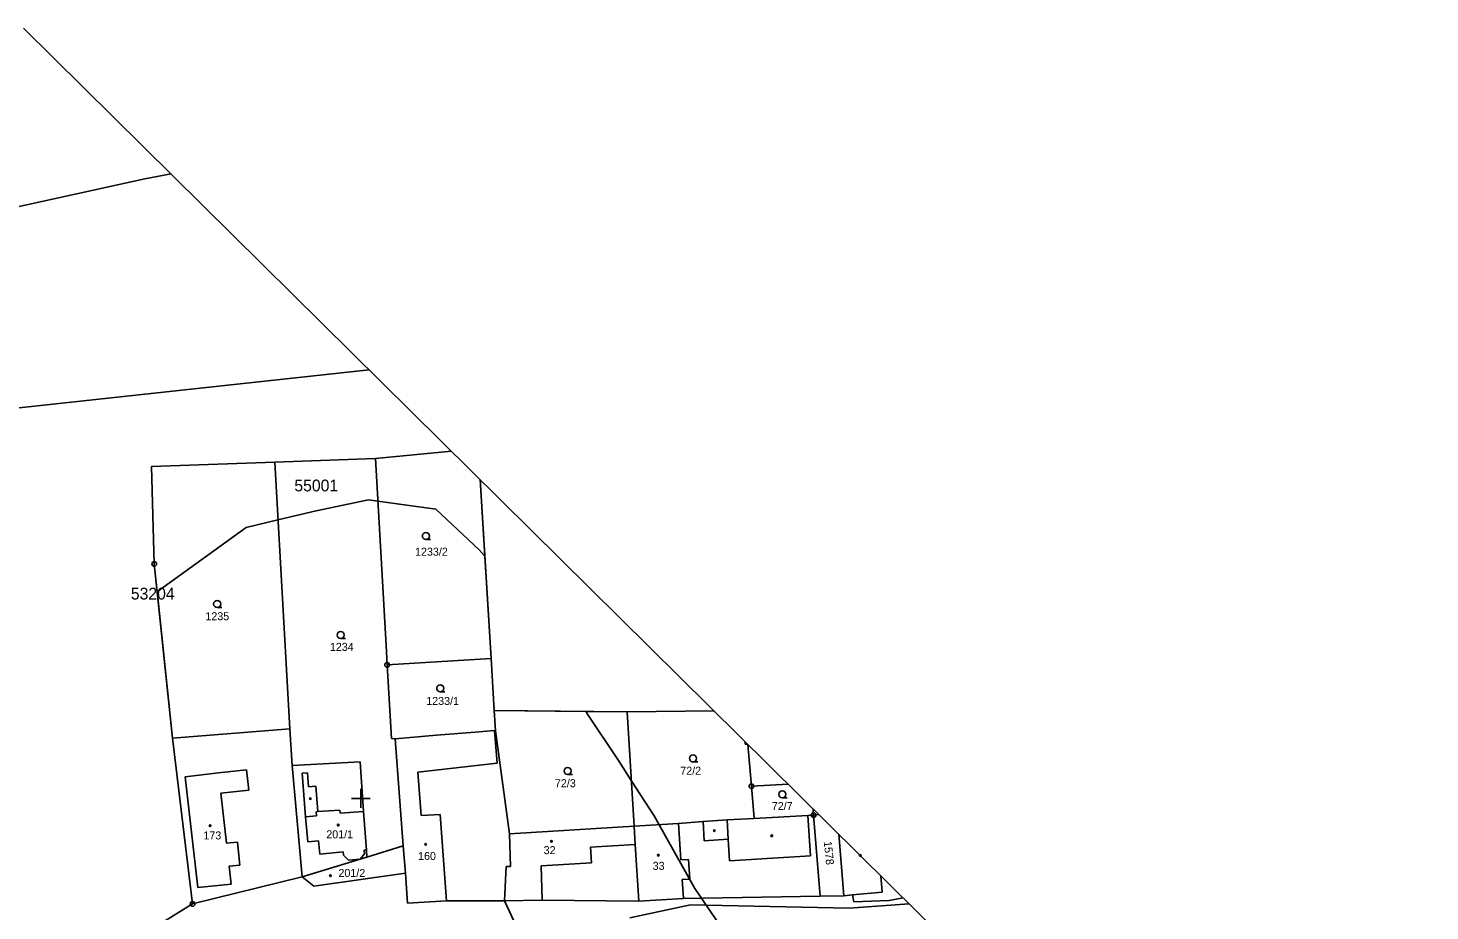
# Model space of a CAD drawing. Extents: x -777175 to -776673, y -1110537 to -1110036.
# Drawn here: x -776970.6 to -776672.9, y -1110223.9 to -1110036.4 of the extents above; entities that cross this region are included whole.
import ezdxf

# ---------------------------------------------------------------- set-up
doc = ezdxf.new("R2010")
doc.units = 0
for name, color, linetype in [('BPEJ', 7, 'Continuous'), ('Katastr_Hranice parcel', 7, 'Continuous'), ('Katastr_Parcelní čísla', 7, 'Continuous'), ('Katastr_Slučkované čáry', 7, 'Continuous'), ('Katastr_Značky kultur', 7, 'Continuous'), ('čtvercová síť', 7, 'Continuous')]:
    doc.layers.add(name, color=color, linetype=linetype)

# ---------------------------------------------------------------- blocks, each defined once
blk = doc.blocks.new('C691')
at = {"layer": 'čtvercová síť'}
for p, q in [((-0.5, 0), (0.5, 0)), ((0, 0.5), (0, -0.5))]:
    blk.add_line(p, q, dxfattribs=at)

msp = doc.modelspace()

# ---------------------------------------------------------------- linework, layer by layer
at = {"layer": 'BPEJ'}
for points in [[(-776943.23, -1110156.15), (-776943.84, -1110150.23), (-776944.43, -1110129.54), (-776918.27, -1110128.61), (-776896.87, -1110127.82), (-776880.71, -1110126.3)], [(-776874.64, -1110132.31), (-776873.64, -1110148.61)], [(-776943.16, -1110156.08), (-776924.3, -1110142.48), (-776917.57, -1110140.89), (-776909.43, -1110138.96), (-776898.38, -1110136.63), (-776896.36, -1110136.9), (-776884.02, -1110138.59), (-776874.85, -1110147.22), (-776873.64, -1110148.61)], [(-776873.64, -1110148.61), (-776872.31, -1110170.3), (-776871.63, -1110181.37), (-776852.23, -1110181.54)], [(-776943.23, -1110156.15), (-776943.16, -1110156.08)], [(-776943.1, -1110157.36), (-776943.23, -1110156.15)], [(-776943.1, -1110157.36), (-776943.16, -1110156.08)], [(-776939.07, -1110224.48), (-776935.71, -1110222.4), (-776940, -1110187.19), (-776943.1, -1110157.36)], [(-776852.23, -1110181.54), (-776843.41, -1110181.62), (-776824.95, -1110181.44)], [(-776852.23, -1110181.54), (-776851.73, -1110182.33), (-776845.13, -1110192.18), (-776842.54, -1110196.21), (-776837.7, -1110203.74), (-776836.65, -1110205.62), (-776829.07, -1110219.13), (-776827.66, -1110221.2), (-776826.66, -1110222.65), (-776822.05, -1110229.41), (-776821.58, -1110229.97), (-776818.14, -1110234.08), (-776814.62, -1110238.29), (-776805.87, -1110248.74), (-776802.05, -1110253.25), (-776793.36, -1110263.5)]]:
    msp.add_lwpolyline(points, dxfattribs=at)
at = {"layer": 'Defpoints'}
msp.add_line((-776672.94, -1110331.74), (-776971.6, -1110036.44), dxfattribs=at)
at = {"layer": 'Katastr_Hranice parcel'}
for points in [[(-777019.23, -1110084.62), (-776945.83, -1110068.47), (-776940.28, -1110067.41)], [(-777071.41, -1110137.39), (-777071.39, -1110137.43), (-777016.29, -1110136.81), (-777017.63, -1110122), (-776898.22, -1110109)], [(-776944.43, -1110129.54), (-776918.27, -1110128.61)], [(-776918.27, -1110128.61), (-776896.87, -1110127.82)], [(-776918.27, -1110128.61), (-776915.03, -1110185.23)], [(-776896.87, -1110127.82), (-776880.71, -1110126.3)], [(-776896.87, -1110127.82), (-776894.63, -1110167.56)], [(-776943.84, -1110150.23), (-776944.43, -1110129.54)], [(-776872.31, -1110170.3), (-776874.64, -1110132.31)], [(-776940, -1110187.19), (-776943.84, -1110150.23)], [(-776894.63, -1110167.56), (-776894.4, -1110171.66)], [(-776894.4, -1110171.66), (-776872.31, -1110170.3)], [(-776872.31, -1110170.3), (-776871.63, -1110181.37)], [(-776893.49, -1110187.3), (-776894.4, -1110171.66)], [(-776871.63, -1110181.37), (-776843.41, -1110181.62)], [(-776871.63, -1110181.37), (-776871.37, -1110185.65)], [(-776843.41, -1110181.62), (-776824.95, -1110181.44)], [(-776841.96, -1110205.94), (-776843.41, -1110181.62)], [(-776940, -1110187.19), (-776915.03, -1110185.23)], [(-776935.71, -1110222.4), (-776940, -1110187.19)], [(-776915.03, -1110185.23), (-776914.58, -1110193.06)], [(-776892.68, -1110187.37), (-776893.49, -1110187.3)], [(-776883.94, -1110186.59), (-776892.68, -1110187.37)], [(-776892.68, -1110187.37), (-776890.97, -1110210.05)], [(-776883.94, -1110186.59), (-776875.69, -1110185.94)], [(-776871.62, -1110185.62), (-776875.69, -1110185.94)], [(-776871.37, -1110185.65), (-776871.62, -1110185.62)], [(-776871.37, -1110185.65), (-776868.38, -1110207.5)], [(-776818.33, -1110188.48), (-776818.33, -1110187.99)], [(-776817.83, -1110188.48), (-776818.33, -1110188.48)], [(-776817.04, -1110197.43), (-776817.78, -1110188.54)], [(-776900.12, -1110192.28), (-776914.58, -1110193.06)], [(-776912.44, -1110216.65), (-776914.58, -1110193.06)], [(-776900.12, -1110192.28), (-776899.38, -1110202.78)], [(-776809.21, -1110197), (-776817.04, -1110197.43)], [(-776816.48, -1110204.27), (-776817.04, -1110197.43)], [(-776899.38, -1110202.78), (-776898.8, -1110210.98)], [(-776803.82, -1110203.55), (-776803.93, -1110202.23)], [(-776868.38, -1110207.5), (-776841.96, -1110205.94)], [(-776832.52, -1110205.37), (-776841.96, -1110205.94)], [(-776841.96, -1110205.94), (-776841.72, -1110209.81)], [(-776827.3, -1110204.95), (-776832.52, -1110205.37)], [(-776822.18, -1110204.58), (-776827.3, -1110204.95)], [(-776816.48, -1110204.27), (-776822.18, -1110204.58)], [(-776805.07, -1110203.65), (-776816.48, -1110204.27)], [(-776803.82, -1110203.55), (-776805.07, -1110203.65)], [(-776802.69, -1110203.45), (-776803.82, -1110203.55)], [(-776803.82, -1110203.55), (-776802.41, -1110220.8)], [(-776868.38, -1110207.5), (-776868.19, -1110214.46)], [(-776797.41, -1110220.68), (-776798.47, -1110207.62)], [(-776898.8, -1110210.98), (-776898.69, -1110212.47)], [(-776890.97, -1110210.05), (-776898.69, -1110212.47)], [(-776890.97, -1110210.05), (-776890.52, -1110215.9)], [(-776841.72, -1110209.81), (-776840.96, -1110221.85)], [(-776900.13, -1110212.92), (-776912.44, -1110216.65)], [(-776898.69, -1110212.47), (-776900.13, -1110212.92)], [(-776869.09, -1110214.44), (-776869.45, -1110221.75)], [(-776868.19, -1110214.46), (-776869.09, -1110214.44)], [(-776935.71, -1110222.4), (-776912.44, -1110216.65)], [(-776912.44, -1110216.65), (-776909.94, -1110218.64)], [(-776909.94, -1110218.64), (-776890.52, -1110215.9)], [(-776890.52, -1110215.9), (-776890.04, -1110222.28)], [(-776831.47, -1110221.26), (-776802.41, -1110220.8)], [(-776802.41, -1110220.8), (-776797.41, -1110220.68)], [(-776795.55, -1110220.51), (-776797.41, -1110220.68)], [(-776795.28, -1110221.95), (-776795.55, -1110220.51)], [(-776951.61, -1110232.24), (-776935.71, -1110222.4)], [(-776881.76, -1110221.77), (-776890.04, -1110222.28)], [(-776881.76, -1110221.77), (-776869.45, -1110221.75)], [(-776869.45, -1110221.75), (-776861.46, -1110221.61)], [(-776862.67, -1110236.36), (-776869.45, -1110221.75)], [(-776861.46, -1110221.61), (-776840.96, -1110221.85)], [(-776842.87, -1110225.4), (-776829.97, -1110222.58)], [(-776831.47, -1110221.26), (-776840.96, -1110221.85)], [(-776829.97, -1110222.58), (-776796.3, -1110223.34)], [(-776796.3, -1110223.34), (-776783.54, -1110222.38)], [(-776787.79, -1110221.67), (-776795.28, -1110221.95)], [(-776784.84, -1110221.11), (-776787.79, -1110221.67)]]:
    msp.add_lwpolyline(points, dxfattribs=at)
at = {"layer": 'Katastr_Slučkované čáry'}
for points in [[(-776871.62, -1110185.62), (-776871.05, -1110192.53)], [(-776930.17, -1110194.6), (-776924.28, -1110193.94)], [(-776924.28, -1110193.94), (-776923.79, -1110198.23)], [(-776871.05, -1110192.53), (-776887.84, -1110194.44)], [(-776937.25, -1110195.4), (-776930.17, -1110194.6)], [(-776937.25, -1110195.4), (-776934.6, -1110218.95)], [(-776912.45, -1110194.65), (-776911.33, -1110194.55)], [(-776911.72, -1110203.95), (-776912.45, -1110194.65)], [(-776911.33, -1110194.55), (-776911.1, -1110197.54)], [(-776887.84, -1110194.44), (-776887.14, -1110203.67)], [(-776923.79, -1110198.23), (-776929.68, -1110198.89)], [(-776929.68, -1110198.89), (-776928.49, -1110209.54)], [(-776911.1, -1110197.54), (-776909.52, -1110197.39)], [(-776909.52, -1110197.39), (-776909.11, -1110202.82)], [(-776909.49, -1110202.85), (-776909.11, -1110202.82)], [(-776909.49, -1110202.85), (-776909.41, -1110203.69)], [(-776909.11, -1110202.82), (-776904.42, -1110202.51)], [(-776904.42, -1110202.51), (-776904.37, -1110203.17)], [(-776904.37, -1110203.17), (-776899.38, -1110202.78)], [(-776909.41, -1110203.69), (-776911.72, -1110203.95)], [(-776911.72, -1110203.95), (-776911.21, -1110209.2)], [(-776883.15, -1110203.42), (-776887.14, -1110203.67)], [(-776883.15, -1110203.42), (-776881.76, -1110221.77)], [(-776832.52, -1110205.37), (-776832.01, -1110213.07)], [(-776827.3, -1110204.95), (-776827.04, -1110209.02)], [(-776821.94, -1110208.7), (-776822.18, -1110204.58)], [(-776805.07, -1110203.65), (-776804.52, -1110212.23)], [(-776911.21, -1110209.2), (-776908.93, -1110208.99)], [(-776908.93, -1110208.99), (-776908.69, -1110211.82)], [(-776827.04, -1110209.02), (-776821.94, -1110208.7)], [(-776821.67, -1110213.27), (-776821.94, -1110208.7)], [(-776928.49, -1110209.54), (-776926.2, -1110209.29)], [(-776926.2, -1110209.29), (-776925.66, -1110214.16)], [(-776908.69, -1110211.82), (-776903.74, -1110211.37)], [(-776903.74, -1110211.37), (-776903.69, -1110212.07)], [(-776900.13, -1110212.92), (-776899.2, -1110211.79)], [(-776899.26, -1110211.03), (-776898.8, -1110210.98)], [(-776899.2, -1110211.79), (-776899.26, -1110211.03)], [(-776851.17, -1110210.37), (-776841.72, -1110209.81)], [(-776851.17, -1110210.37), (-776850.96, -1110213.71)], [(-776925.66, -1110214.16), (-776927.94, -1110214.41)], [(-776927.94, -1110214.41), (-776927.52, -1110218.19)], [(-776903.69, -1110212.07), (-776902.6, -1110213.11)], [(-776902.6, -1110213.11), (-776900.13, -1110212.92)], [(-776861.66, -1110214.34), (-776850.96, -1110213.71)], [(-776861.66, -1110214.34), (-776861.46, -1110221.61)], [(-776832.01, -1110213.07), (-776830.41, -1110212.96)], [(-776830.41, -1110212.96), (-776830.14, -1110217.16)], [(-776804.52, -1110212.23), (-776821.67, -1110213.27)], [(-776830.14, -1110217.16), (-776831.73, -1110217.26)], [(-776831.73, -1110217.26), (-776831.47, -1110221.26)], [(-776789.56, -1110216.44), (-776789.26, -1110219.94)], [(-776934.6, -1110218.95), (-776927.52, -1110218.19)], [(-776789.26, -1110219.94), (-776795.55, -1110220.51)]]:
    msp.add_lwpolyline(points, dxfattribs=at)
at = {"layer": 'Katastr_Značky kultur'}
for p, q in [((-776886.16, -1110145.05), (-776885.16, -1110145.05)), ((-776943.89, -1110150.23), (-776943.79, -1110150.23)), ((-776930.48, -1110159.48), (-776929.48, -1110159.48)), ((-776904.25, -1110166.07), (-776903.25, -1110166.07)), ((-776894.45, -1110171.66), (-776894.35, -1110171.66)), ((-776883.12, -1110177.38), (-776882.12, -1110177.38)), ((-776829.43, -1110192.28), (-776828.43, -1110192.28)), ((-776856.05, -1110194.94), (-776855.05, -1110194.94)), ((-776817.09, -1110197.43), (-776816.99, -1110197.43)), ((-776810.46, -1110199.9), (-776809.46, -1110199.9)), ((-776803.87, -1110203.55), (-776803.77, -1110203.55)), ((-776935.76, -1110222.4), (-776935.66, -1110222.4))]:
    msp.add_line(p, q, dxfattribs=at)
for centre, radius in [((-776886.16, -1110144.3), 0.75), ((-776943.84, -1110150.23), 0.499), ((-776930.48, -1110158.73), 0.75), ((-776904.25, -1110165.32), 0.75), ((-776894.4, -1110171.66), 0.499), ((-776883.12, -1110176.63), 0.75), ((-776829.43, -1110191.53), 0.75), ((-776856.05, -1110194.19), 0.75), ((-776817.04, -1110197.43), 0.499), ((-776910.69, -1110200.05), 0.175), ((-776810.46, -1110199.15), 0.75), ((-776803.82, -1110203.55), 0.499), ((-776931.98, -1110205.79), 0.175), ((-776904.78, -1110205.68), 0.175), ((-776859.5, -1110209.14), 0.175), ((-776824.89, -1110206.87), 0.175), ((-776812.7, -1110207.95), 0.175), ((-776886.2, -1110209.76), 0.175), ((-776836.79, -1110212.08), 0.175), ((-776793.92, -1110212.14), 0.175), ((-776906.42, -1110216.42), 0.175), ((-776935.71, -1110222.4), 0.499)]:
    msp.add_circle(centre, radius, dxfattribs=at)

# ---------------------------------------------------------------- block references
at = {"layer": 'čtvercová síť', "xscale": 4, "yscale": 4}
msp.add_blockref('C691', (-776899.99, -1110200), dxfattribs=at)

# ---------------------------------------------------------------- texts
at = {"layer": 'BPEJ'}
for s, p in [('55001', (-776914.09, -1110134.82)), ('53204', (-776948.81, -1110157.78))]:
    msp.add_text(s, height=2.5, dxfattribs=at).set_placement(p)
at = {"layer": 'Katastr_Parcelní čísla'}
for s, p in [('1233/2', (-776888.46, -1110148.48)), ('1235', (-776932.98, -1110162.18)), ('1234', (-776906.55, -1110168.69)), ('1233/1', (-776886.08, -1110180.17)), ('72/2', (-776832.14, -1110194.98)), ('72/3', (-776858.76, -1110197.64)), ('72/7', (-776812.7, -1110202.48)), ('173', (-776933.4, -1110208.72)), ('201/1', (-776907.31, -1110208.49)), ('160', (-776887.82, -1110213.09)), ('32', (-776861.15, -1110211.85)), ('201/2', (-776904.73, -1110216.69)), ('33', (-776838, -1110215.18))]:
    msp.add_text(s, height=1.7, dxfattribs=at).set_placement(p)
msp.add_text('1578', height=1.7, rotation=275.8361, dxfattribs=at).set_placement((-776801.68, -1110209.17))

doc.saveas('drawing.dxf')
